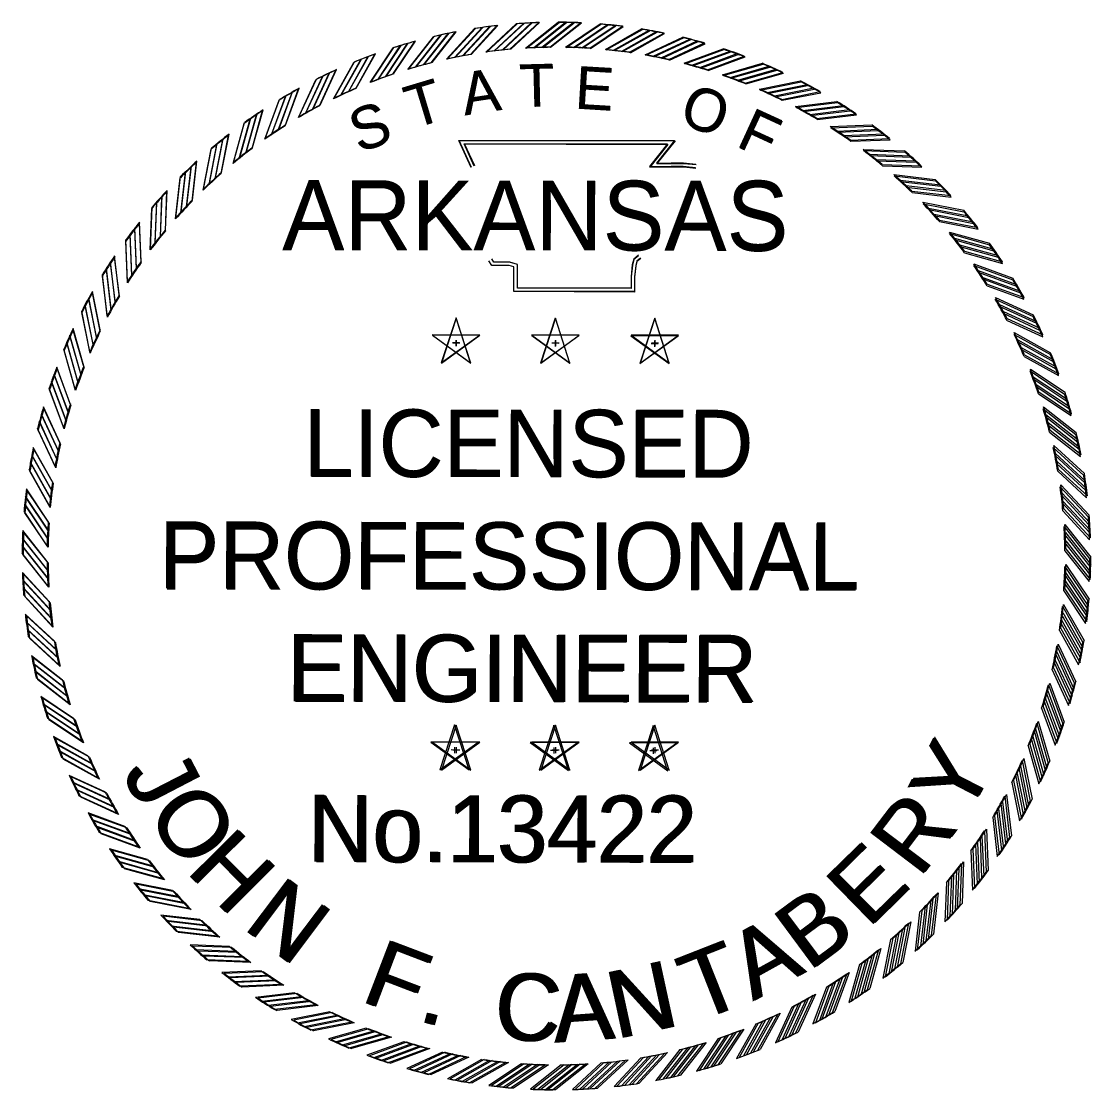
# Model space of a CAD drawing. Extents: x 1212896 to 1368412, y 378476 to 478763.
# Drawn here: x 1355477 to 1367632, y 379003 to 391149 of the extents above; entities that cross this region are included whole.
import ezdxf

# ---------------------------------------------------------------- set-up
doc = ezdxf.new("R2010")
doc.units = 0
doc.layers.add('Default', color=7, linetype='Continuous')

# ---------------------------------------------------------------- blocks, each defined once
blk = doc.blocks.new('STAR')
at = {"layer": 'Default'}
for p, q in [((-0.0001, 0.0615), (-0.0366, -0.0504)), ((0.0362, -0.0503), (0, 0.0617)), ((0.0587, 0.0188), (-0.059, 0.0189)), ((-0.0589, 0.0188), (0.0363, -0.0505)), ((-0.0365, -0.0503), (0.0589, 0.0188)), ((-0.0085, 0), (0.009, 0)), ((0, 0.0063), (0, -0.0085))]:
    blk.add_line(p, q, dxfattribs=at)
blk = doc.blocks.new('RP')
at = {"layer": 'Default'}
for p, q in [((-0.0781, 1.2656), (0.003, 1.33)), ((-0.058, 1.2667), (0.0216, 1.3299)), ((-0.0375, 1.2674), (0.0405, 1.3294)), ((-0.0176, 1.2679), (0.059, 1.3287))]:
    blk.add_line(p, q, dxfattribs=at)
for radius, start, end in [(1.33, 87.4562, 89.8699), (1.268, 90.7933, 93.5307)]:
    blk.add_arc((0, 0), radius, start, end, dxfattribs=at)

msp = doc.modelspace()

# ---------------------------------------------------------------- linework, layer by layer
at = {"layer": 'Default'}
for points in [[(1360586, 389489), (1360444, 389796), (1362896, 389797), (1362691, 389540), (1362858, 389542), (1362997, 389544), (1363136, 389529)], [(1360591, 389491), (1360450, 389798), (1362902, 389791), (1362696, 389534), (1362863, 389536), (1363002, 389537), (1363141, 389522)], [(1360621, 389505), (1360505, 389757), (1362816, 389758), (1362610, 389500), (1362858, 389503), (1362995, 389505), (1363132, 389490)], [(1360626, 389507), (1360511, 389759), (1362821, 389752), (1362615, 389495), (1362863, 389497), (1363000, 389498), (1363137, 389483)], [(1362485, 388492), (1362434, 388450), (1362416, 388384), (1362401, 388252), (1362401, 388119), (1361110, 388119), (1361110, 388309), (1361110, 388388), (1361022, 388415), (1360842, 388415), (1360819, 388451)], [(1362487, 388487), (1362435, 388445), (1362417, 388379), (1362402, 388247), (1362401, 388114), (1361110, 388119), (1361111, 388309), (1361111, 388388), (1361023, 388416), (1360843, 388416), (1360820, 388451)], [(1362510, 388461), (1362468, 388427), (1362454, 388377), (1362440, 388249), (1362440, 388080), (1361071, 388080), (1361071, 388309), (1361071, 388360), (1361016, 388377), (1360821, 388377), (1360787, 388429)], [(1362511, 388457), (1362469, 388423), (1362455, 388372), (1362441, 388245), (1362440, 388075), (1361071, 388080), (1361072, 388309), (1361072, 388360), (1361017, 388377), (1360822, 388377), (1360788, 388430)]]:
    msp.add_lwpolyline(points, dxfattribs=at)

# ---------------------------------------------------------------- block references
for name, p, xscale, yscale, rotation in [('RP', (1361560, 385077), 4558.827671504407, 4558.827671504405, 13.500000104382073), ('RP', (1361549, 385075), 4558.827671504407, 4558.827671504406, 13.304199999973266), ('RP', (1361560, 385077), 4558.827671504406, 4558.827671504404, 9.000000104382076), ('RP', (1361549, 385075), 4558.827671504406, 4558.827671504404, 8.80419999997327), ('RP', (1361560, 385077), 4558.8276715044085, 4558.827671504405, 4.500000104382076), ('RP', (1361549, 385075), 4558.8276715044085, 4558.827671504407, 4.304199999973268), ('RP', (1361560, 385077), 4558.827671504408, 4558.827671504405, 1.0438208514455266e-07), ('RP', (1361549, 385075), 4558.827671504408, 4558.827671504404, -0.19580000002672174), ('RP', (1361560, 385077), 4558.827671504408, 4558.827671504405, -4.499999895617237), ('RP', (1361549, 385075), 4558.827671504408, 4558.827671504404, -4.695800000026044), ('RP', (1361560, 385077), 4558.8276715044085, 4558.827671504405, -8.999999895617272), ('RP', (1361549, 385075), 4558.827671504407, 4558.827671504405, -9.19580000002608), ('RP', (1361560, 385077), 4558.827671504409, 4558.827671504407, -13.499999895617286), ('RP', (1361549, 385075), 4558.827671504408, 4558.827671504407, -13.695800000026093), ('RP', (1361560, 385077), 4558.8276715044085, 4558.827671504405, 18.000000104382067), ('RP', (1361549, 385075), 4558.827671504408, 4558.827671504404, 17.80419999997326), ('RP', (1361560, 385077), 4558.8276715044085, 4558.827671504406, -17.999999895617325), ('RP', (1361549, 385075), 4558.827671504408, 4558.827671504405, -18.195800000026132), ('RP', (1361549, 385075), 4558.827671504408, 4558.827671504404, 22.304199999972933), ('RP', (1361560, 385077), 4558.827671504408, 4558.827671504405, -22.499999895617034), ('RP', (1361549, 385075), 4558.827671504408, 4558.827671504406, -22.695800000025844), ('RP', (1361560, 385077), 4558.827671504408, 4558.827671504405, 22.500000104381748), ('RP', (1361560, 385077), 4558.827671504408, 4558.827671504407, 27.000000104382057), ('RP', (1361549, 385075), 4558.827671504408, 4558.827671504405, 26.80419999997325), ('RP', (1361560, 385077), 4558.827671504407, 4558.827671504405, -26.999999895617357), ('RP', (1361549, 385075), 4558.827671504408, 4558.827671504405, -27.19580000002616), ('RP', (1361560, 385077), 4558.827671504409, 4558.827671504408, -31.49999989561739), ('RP', (1361560, 385077), 4558.827671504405, 4558.827671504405, 31.500000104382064), ('RP', (1361549, 385075), 4558.827671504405, 4558.827671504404, 31.30419999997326), ('RP', (1361549, 385075), 4558.8276715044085, 4558.827671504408, -31.695800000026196), ('RP', (1361560, 385077), 4558.8276715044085, 4558.827671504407, -35.99999989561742), ('RP', (1361560, 385077), 4558.827671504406, 4558.827671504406, 36.00000010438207), ('RP', (1361549, 385075), 4558.827671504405, 4558.827671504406, 35.804199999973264), ('RP', (1361549, 385075), 4558.827671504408, 4558.827671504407, -36.195800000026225), ('RP', (1361560, 385077), 4558.827671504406, 4558.827671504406, 40.50000010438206), ('RP', (1361549, 385075), 4558.827671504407, 4558.827671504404, 40.30419999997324), ('RP', (1361560, 385077), 4558.827671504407, 4558.827671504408, -40.49999989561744), ('RP', (1361549, 385075), 4558.827671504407, 4558.827671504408, -40.69580000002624), ('RP', (1361560, 385077), 4558.827671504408, 4558.827671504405, -44.99999989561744), ('RP', (1361549, 385075), 4558.827671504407, 4558.827671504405, -45.19580000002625), ('RP', (1361560, 385077), 4558.827671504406, 4558.827671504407, 45.00000010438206), ('RP', (1361549, 385075), 4558.827671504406, 4558.827671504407, 44.80419999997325), ('RP', (1361560, 385077), 4558.827671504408, 4558.8276715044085, 49.500000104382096), ('RP', (1361549, 385075), 4558.827671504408, 4558.8276715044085, 49.30419999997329), ('RP', (1361560, 385077), 4558.827671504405, 4558.827671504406, -49.499999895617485), ('RP', (1361549, 385075), 4558.827671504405, 4558.827671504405, -49.695800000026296), ('RP', (1361560, 385077), 4558.827671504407, 4558.827671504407, 54.00000010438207), ('RP', (1361549, 385075), 4558.827671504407, 4558.827671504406, 53.804199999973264), ('RP', (1361560, 385077), 4558.827671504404, 4558.827671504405, -53.999999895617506), ('RP', (1361549, 385075), 4558.827671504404, 4558.827671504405, -54.1958000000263), ('RP', (1361549, 385075), 4558.827671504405, 4558.827671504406, 58.304199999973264), ('RP', (1361560, 385077), 4558.827671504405, 4558.827671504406, -58.49999989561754), ('RP', (1361549, 385075), 4558.827671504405, 4558.827671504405, -58.695800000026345), ('RP', (1361560, 385077), 4558.827671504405, 4558.827671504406, 58.50000010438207), ('RP', (1361560, 385077), 4558.827671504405, 4558.827671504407, -62.999999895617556), ('RP', (1361549, 385075), 4558.827671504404, 4558.827671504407, -63.19580000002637), ('RP', (1361549, 385075), 4558.827671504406, 4558.827671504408, 62.804199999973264), ('RP', (1361560, 385077), 4558.827671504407, 4558.827671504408, 63.000000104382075), ('STAR', (1360413, 387500), 4558.827671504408, 4558.827671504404, -0.19580000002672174), ('STAR', (1360415, 387498), 4558.827671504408, 4558.827671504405, 1.0438208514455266e-07), ('STAR', (1361541, 387496), 4558.827671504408, 4558.827671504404, -0.19580000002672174), ('STAR', (1361543, 387498), 4558.827671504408, 4558.827671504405, 1.0438208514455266e-07), ('STAR', (1362669, 387492), 4558.827671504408, 4558.827671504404, -0.19580000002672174), ('STAR', (1362671, 387498), 4558.827671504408, 4558.827671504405, 1.0438208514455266e-07), ('RP', (1361549, 385075), 4558.827671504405, 4558.827671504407, 67.30419999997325), ('RP', (1361560, 385077), 4558.827671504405, 4558.827671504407, 67.50000010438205), ('RP', (1361549, 385075), 4558.827671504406, 4558.827671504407, -67.69580000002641), ('RP', (1361560, 385077), 4558.827671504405, 4558.827671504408, -67.49999989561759), ('RP', (1361549, 385075), 4558.827671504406, 4558.827671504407, -72.19580000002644), ('RP', (1361560, 385077), 4558.827671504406, 4558.827671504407, -71.99999989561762), ('RP', (1361549, 385075), 4558.827671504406, 4558.8276715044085, 71.80419999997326), ('RP', (1361560, 385077), 4558.827671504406, 4558.8276715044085, 72.00000010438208), ('RP', (1361549, 385075), 4558.827671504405, 4558.827671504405, -76.69580000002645), ('RP', (1361560, 385077), 4558.827671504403, 4558.827671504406, -76.49999989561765), ('RP', (1361549, 385075), 4558.827671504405, 4558.827671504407, 76.30419999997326), ('RP', (1361560, 385077), 4558.827671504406, 4558.8276715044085, 76.50000010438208), ('RP', (1361549, 385075), 4558.827671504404, 4558.827671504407, 80.80419999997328), ('RP', (1361560, 385077), 4558.827671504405, 4558.827671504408, 81.0000001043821), ('RP', (1361549, 385075), 4558.827671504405, 4558.827671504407, -81.19580000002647), ('RP', (1361560, 385077), 4558.827671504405, 4558.827671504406, -80.99999989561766), ('RP', (1361549, 385075), 4558.827671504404, 4558.827671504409, 85.30419999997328), ('RP', (1361560, 385077), 4558.827671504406, 4558.8276715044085, 85.50000010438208), ('RP', (1361549, 385075), 4558.827671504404, 4558.827671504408, -85.69580000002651), ('RP', (1361560, 385077), 4558.827671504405, 4558.827671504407, -85.49999989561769), ('RP', (1361549, 385075), 4558.827671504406, 4558.8276715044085, 89.80419999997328), ('RP', (1361560, 385077), 4558.827671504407, 4558.827671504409, 90.0000001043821), ('RP', (1361549, 385075), 4558.827671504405, 4558.8276715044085, -90.19580000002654), ('RP', (1361560, 385077), 4558.827671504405, 4558.827671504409, -89.99999989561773), ('RP', (1361549, 385075), 4558.827671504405, 4558.8276715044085, -94.69580000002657), ('RP', (1361560, 385077), 4558.827671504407, 4558.827671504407, -94.49999989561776), ('RP', (1361549, 385075), 4558.827671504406, 4558.827671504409, 94.30419999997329), ('RP', (1361560, 385077), 4558.827671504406, 4558.8276715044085, 94.5000001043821), ('RP', (1361549, 385075), 4558.827671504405, 4558.827671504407, -99.19580000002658), ('RP', (1361560, 385077), 4558.827671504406, 4558.827671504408, -98.99999989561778), ('RP', (1361549, 385075), 4558.827671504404, 4558.827671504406, 98.8041999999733), ('RP', (1361560, 385077), 4558.827671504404, 4558.827671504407, 99.0000001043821), ('RP', (1361549, 385075), 4558.827671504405, 4558.827671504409, 103.30419999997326), ('RP', (1361560, 385077), 4558.827671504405, 4558.827671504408, 103.50000010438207), ('RP', (1361549, 385075), 4558.827671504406, 4558.827671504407, -103.69580000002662), ('RP', (1361560, 385077), 4558.827671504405, 4558.827671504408, -103.49999989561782), ('RP', (1361560, 385077), 4558.827671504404, 4558.827671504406, -107.99999989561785), ('RP', (1361549, 385075), 4558.827671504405, 4558.82767150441, 107.80419999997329), ('RP', (1361560, 385077), 4558.827671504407, 4558.827671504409, 108.0000001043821), ('RP', (1361549, 385075), 4558.827671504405, 4558.827671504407, -108.19580000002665), ('RP', (1361549, 385075), 4558.827671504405, 4558.827671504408, 112.30419999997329), ('STAR', (1360397, 382876), 4558.827671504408, 4558.827671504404, -0.19580000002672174), ('STAR', (1360415, 382874), 4558.827671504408, 4558.827671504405, 1.0438208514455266e-07), ('STAR', (1361525, 382872), 4558.827671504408, 4558.827671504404, -0.19580000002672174), ('STAR', (1361543, 382874), 4558.827671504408, 4558.827671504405, 1.0438208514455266e-07), ('STAR', (1362653, 382868), 4558.827671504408, 4558.827671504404, -0.19580000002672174), ('STAR', (1362671, 382874), 4558.827671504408, 4558.827671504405, 1.0438208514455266e-07), ('RP', (1361549, 385075), 4558.827671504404, 4558.8276715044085, -112.69580000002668), ('RP', (1361560, 385077), 4558.827671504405, 4558.8276715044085, -112.49999989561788), ('RP', (1361560, 385077), 4558.827671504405, 4558.827671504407, 112.5000001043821), ('RP', (1361560, 385077), 4558.827671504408, 4558.8276715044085, -116.9999998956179), ('RP', (1361549, 385075), 4558.827671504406, 4558.827671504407, 116.80419999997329), ('RP', (1361560, 385077), 4558.827671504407, 4558.827671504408, 117.0000001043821), ('RP', (1361549, 385075), 4558.827671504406, 4558.8276715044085, -117.19580000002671), ('RP', (1361549, 385075), 4558.827671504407, 4558.827671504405, 121.30419999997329), ('RP', (1361560, 385077), 4558.827671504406, 4558.827671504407, 121.5000001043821), ('RP', (1361549, 385075), 4558.827671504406, 4558.827671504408, -121.69580000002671), ('RP', (1361560, 385077), 4558.827671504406, 4558.8276715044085, -121.4999998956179), ('RP', (1361549, 385075), 4558.827671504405, 4558.827671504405, 125.80419999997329), ('RP', (1361549, 385075), 4558.827671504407, 4558.827671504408, -126.19580000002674), ('RP', (1361560, 385077), 4558.827671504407, 4558.8276715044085, -125.99999989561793), ('RP', (1361560, 385077), 4558.827671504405, 4558.827671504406, 126.00000010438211), ('RP', (1361549, 385075), 4558.827671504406, 4558.827671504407, -130.6958000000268), ('RP', (1361560, 385077), 4558.827671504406, 4558.827671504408, -130.49999989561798), ('RP', (1361549, 385075), 4558.827671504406, 4558.827671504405, 130.3041999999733), ('RP', (1361560, 385077), 4558.827671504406, 4558.827671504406, 130.50000010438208), ('RP', (1361549, 385075), 4558.827671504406, 4558.827671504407, 134.8041999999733), ('RP', (1361560, 385077), 4558.827671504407, 4558.827671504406, 135.00000010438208), ('RP', (1361549, 385075), 4558.827671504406, 4558.827671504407, -135.19580000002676), ('RP', (1361560, 385077), 4558.827671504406, 4558.827671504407, -134.99999989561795), ('RP', (1361549, 385075), 4558.827671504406, 4558.827671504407, 139.30419999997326), ('RP', (1361560, 385077), 4558.827671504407, 4558.827671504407, 139.50000010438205), ('RP', (1361549, 385075), 4558.827671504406, 4558.827671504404, -139.69580000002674), ('RP', (1361560, 385077), 4558.827671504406, 4558.827671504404, -139.49999989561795), ('RP', (1361549, 385075), 4558.8276715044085, 4558.827671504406, 143.8041999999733), ('RP', (1361549, 385075), 4558.827671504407, 4558.827671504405, -144.19580000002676), ('RP', (1361560, 385077), 4558.827671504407, 4558.827671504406, -143.99999989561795), ('RP', (1361560, 385077), 4558.8276715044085, 4558.827671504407, 144.00000010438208), ('RP', (1361560, 385077), 4558.827671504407, 4558.827671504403, -148.49999989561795), ('RP', (1361549, 385075), 4558.827671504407, 4558.827671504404, 148.3041999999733), ('RP', (1361560, 385077), 4558.827671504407, 4558.827671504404, 148.50000010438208), ('RP', (1361549, 385075), 4558.827671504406, 4558.827671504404, -148.69580000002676), ('RP', (1361560, 385077), 4558.827671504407, 4558.827671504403, -152.99999989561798), ('RP', (1361549, 385075), 4558.827671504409, 4558.827671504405, 152.8041999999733), ('RP', (1361560, 385077), 4558.827671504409, 4558.827671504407, 153.00000010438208), ('RP', (1361549, 385075), 4558.827671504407, 4558.827671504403, -153.1958000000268), ('RP', (1361549, 385075), 4558.827671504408, 4558.827671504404, 157.3041999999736), ('RP', (1361560, 385077), 4558.827671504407, 4558.827671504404, 157.50000010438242), ('RP', (1361549, 385075), 4558.827671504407, 4558.827671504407, -157.6958000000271), ('RP', (1361560, 385077), 4558.827671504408, 4558.827671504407, -157.4999998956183), ('RP', (1361549, 385075), 4558.827671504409, 4558.827671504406, 161.8041999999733), ('RP', (1361560, 385077), 4558.8276715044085, 4558.827671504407, 162.00000010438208), ('RP', (1361549, 385075), 4558.827671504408, 4558.827671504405, -162.19580000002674), ('RP', (1361560, 385077), 4558.8276715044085, 4558.827671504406, -161.99999989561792), ('RP', (1361549, 385075), 4558.827671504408, 4558.827671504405, 166.3041999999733), ('RP', (1361560, 385077), 4558.8276715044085, 4558.827671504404, 166.50000010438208), ('RP', (1361549, 385075), 4558.827671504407, 4558.827671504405, -166.69580000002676), ('RP', (1361560, 385077), 4558.827671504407, 4558.827671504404, -166.49999989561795), ('RP', (1361549, 385075), 4558.827671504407, 4558.827671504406, 170.8041999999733), ('RP', (1361560, 385077), 4558.827671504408, 4558.827671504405, 171.00000010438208), ('RP', (1361549, 385075), 4558.827671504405, 4558.827671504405, -171.19580000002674), ('RP', (1361560, 385077), 4558.827671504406, 4558.827671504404, -170.99999989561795), ('RP', (1361549, 385075), 4558.827671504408, 4558.827671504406, 175.3041999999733), ('RP', (1361560, 385077), 4558.827671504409, 4558.827671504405, 175.50000010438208), ('RP', (1361549, 385075), 4558.8276715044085, 4558.827671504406, 179.8041999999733), ('RP', (1361560, 385077), 4558.827671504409, 4558.827671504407, -179.99999989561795), ('RP', (1361549, 385075), 4558.827671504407, 4558.827671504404, -175.69580000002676), ('RP', (1361560, 385077), 4558.827671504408, 4558.827671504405, -175.49999989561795)]:
    msp.add_blockref(name, p, dxfattribs=dict(at, xscale=xscale, yscale=yscale, rotation=rotation))

# ---------------------------------------------------------------- texts
for s, height, rotation, p in [('T', 484, 1.4789, (1361136, 390176)), ('T', 484, 1.2831, (1361143, 390175)), ('A', 484, 8.6788, (1360511, 390079)), ('A', 484, 8.483, (1360518, 390081)), ('E', 484, 356.672, (1361755, 390161)), ('E', 484, 356.4762, (1361762, 390159)), ('T', 484, 16.9015, (1359924, 389926)), ('T', 484, 16.7057, (1359930, 389930)), ('O', 484, 341.2218, (1362929, 389995)), ('O', 484, 341.026, (1362936, 389989)), ('S', 484, 19.7726, (1359309, 389650)), ('S', 484, 19.5768, (1359314, 389656)), ('F', 484, 335.3628, (1363581, 389740)), ('F', 484, 335.167, (1363587, 389731)), ('ARKANSAS', 789.4, 0, (1358440, 388550)), ('ARKANSAS', 789.4, 359.8042, (1358441, 388559)), ('LICENSED', 764.2, 359.8042, (1358678, 385981)), ('LICENSED', 764.2, 0, (1358685, 385973)), ('PROFESSIONAL', 764.24, 359.8042, (1357036, 384708)), ('PROFESSIONAL', 764.24, 0, (1357047, 384695)), ('ENGINEER', 764.2, 359.8042, (1358487, 383425)), ('ENGINEER', 764.2, 0, (1358503, 383417)), ('Y', 764, 62.5392, (1366208, 382076)), ('Y', 764, 62.735, (1366229, 382093)), ('J', 764, 297.2813, (1356609, 382619)), ('J', 764, 297.4771, (1356628, 382604)), ('O', 764, 304.1899, (1356880, 382150)), ('O', 764, 304.3857, (1356900, 382136)), ('No.13422', 761.2, 359.8042, (1358722, 381603)), ('No.13422', 761.2, 0, (1358744, 381595)), ('R', 764, 52.7437, (1365675, 381403)), ('R', 764, 52.9395, (1365698, 381419)), ('H', 764, 314.7447, (1357331, 381492)), ('H', 764, 314.9405, (1357354, 381479)), ('E', 764, 44.306, (1365093, 380834)), ('E', 764, 44.5018, (1365117, 380848)), ('N', 764, 322.9417, (1357976, 380853)), ('N', 764, 323.1375, (1358001, 380842)), ('B', 764, 36.505, (1364418, 380348)), ('B', 764, 36.7008, (1364445, 380359)), ('A', 764, 28.8562, (1363783, 380014)), ('A', 764, 29.052, (1363811, 380024)), ('F', 764, 339.0288, (1359310, 380025)), ('F', 764, 339.2246, (1359338, 380019)), ('T', 764, 21.4329, (1363148, 379775)), ('T', 764, 21.6287, (1363176, 379782)), ('N', 764, 12.0703, (1362226, 379585)), ('N', 764, 12.2661, (1362255, 379589)), ('C', 764, 356.1028, (1360827, 379596)), ('C', 764, 356.2986, (1360856, 379595)), ('A', 764, 3.9092, (1361528, 379545)), ('A', 764, 4.105, (1361557, 379547)), ('.', 764, 344.7037, (1359962, 379799)), ('.', 764, 344.8995, (1359990, 379795))]:
    msp.add_text(s, height=height, rotation=rotation, dxfattribs=at).set_placement(p)

doc.saveas('drawing.dxf')
